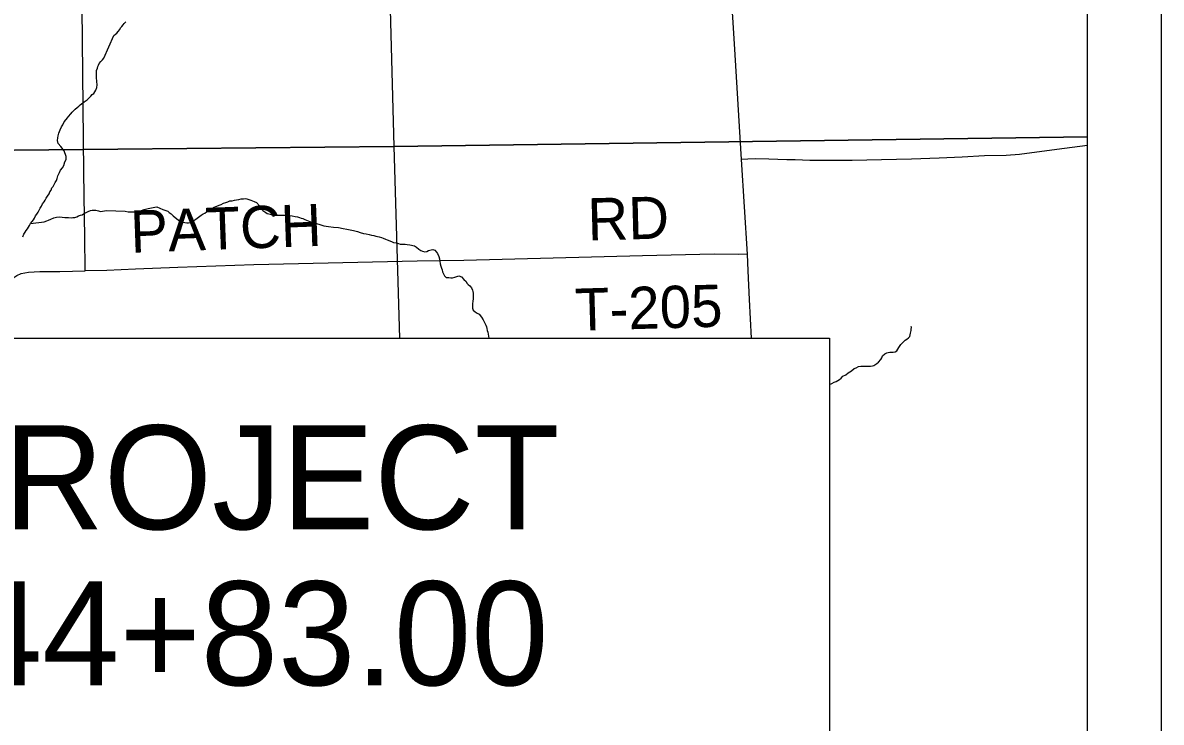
# Model space of a CAD drawing. Extents: x 10.6 to 44.6, y -2.6 to 23.4.
# Drawn here: x 18.57 to 20.103, y 19.074 to 20.016 of the extents above; entities that cross this region are included whole.
import ezdxf

# ---------------------------------------------------------------- set-up
doc = ezdxf.new("R2010")
doc.units = 0
for name, color, linetype in [('GM_X_County', 7, 'Continuous'), ('GM_X_County_Road', 7, 'Continuous'), ('GM_X_Minor_River', 7, 'Continuous'), ('GM_X_Section', 7, 'Continuous'), ('GM_X_Township', 7, 'Continuous'), ('GM_X_Township_Road', 7, 'Continuous'), ('GM_X_Township_Road_Text', 7, 'Continuous'), ('SH_Border', 7, 'Continuous'), ('SH_Data', 7, 'Continuous'), ('SH_Text', 7, 'Continuous')]:
    doc.layers.add(name, color=color, linetype=linetype)

msp = doc.modelspace()

# ---------------------------------------------------------------- linework, layer by layer
at = {"layer": 'GM_X_County'}
msp.add_lwpolyline([(20.0033, 15.5302), (20.0033, 22.3267), (13.2033, 22.3267), (13.2033, 15.5267), (19.8413, 15.5267)], dxfattribs=at)
at = {"layer": 'GM_X_County_Road'}
for points in [[(18.6535, 19.6817), (18.6533, 19.7284), (18.6525, 19.7533), (18.6516, 19.8149), (18.6497, 20.0361), (18.6472, 20.3469), (18.6468, 20.3934), (18.645, 20.5569), (18.6444, 20.6072), (18.643, 20.7692), (18.6417, 20.8913), (18.6416, 20.9277), (18.6445, 20.9403), (18.6498, 20.9497), (18.669, 20.9792), (18.7118, 21.0385)], [(19.5512, 19.5913), (19.5484, 19.6433), (19.5465, 19.6819), (19.5455, 19.7043), (19.5377, 19.8318), (19.5279, 19.9874), (19.5216, 20.0873), (19.5206, 20.1073), (19.5206, 20.1237), (19.5228, 20.1393), (19.526, 20.1578), (19.5311, 20.1832), (19.5709, 20.373), (19.5968, 20.5034), (19.6117, 20.5772), (19.6346, 20.6932), (19.6468, 20.7569), (19.6737, 20.9017), (19.6783, 20.9093)], [(18.5472, 19.661), (18.552, 19.6675), (18.5574, 19.6727), (18.5616, 19.6756), (18.5673, 19.6782), (18.5772, 19.68), (18.5926, 19.6811), (18.6194, 19.6811), (18.6535, 19.6817)]]:
    msp.add_lwpolyline(points, dxfattribs=at)
at = {"layer": 'GM_X_Minor_River'}
for points in [[(18.6789, 19.9682), (18.6923, 19.9989), (18.6942, 20.0004), (18.6961, 20.002), (18.698, 20.0043), (18.7002, 20.0069), (18.7013, 20.0089), (18.7028, 20.0108), (18.7047, 20.0131), (18.7062, 20.015), (18.7085, 20.0173)], [(18.6114, 19.7972), (18.6132, 19.8007), (18.6151, 19.8034), (18.6158, 19.8064), (18.6168, 19.8099), (18.619, 19.8141), (18.6205, 19.8172), (18.6231, 19.8207), (18.6249, 19.8237), (18.6263, 19.8287), (18.6281, 19.8318), (18.6281, 19.836), (18.6252, 19.8435), (18.6209, 19.8495), (18.6174, 19.8532), (18.6162, 19.8574), (18.6169, 19.8608), (18.6172, 19.8635), (18.6183, 19.8673), (18.6197, 19.8719), (18.6219, 19.8757), (18.6234, 19.8784), (18.6255, 19.8827), (18.6278, 19.8858), (18.6296, 19.8877), (18.6311, 19.8896), (18.6341, 19.8931), (18.6359, 19.8954), (18.6378, 19.8974), (18.64, 19.8997), (18.6426, 19.9017), (18.6449, 19.9036), (18.6467, 19.9055), (18.6486, 19.9067), (18.652, 19.9095), (18.6561, 19.9122), (18.6591, 19.9149), (18.661, 19.9169), (18.6632, 19.9192), (18.6651, 19.9208), (18.668, 19.925), (18.6691, 19.9285), (18.6698, 19.9323), (18.6693, 19.9368), (18.6688, 19.9421), (18.6687, 19.9448), (18.6687, 19.9482), (18.669, 19.9516), (18.67, 19.9547), (18.6708, 19.957), (18.6715, 19.9589), (18.6726, 19.9612), (18.6748, 19.9639), (18.6767, 19.9659), (18.6789, 19.9682)], [(18.5695, 19.7275), (18.5709, 19.7314), (18.5728, 19.7341), (18.5743, 19.736), (18.5757, 19.7383), (18.5772, 19.7406), (18.5787, 19.7429), (18.5801, 19.7456), (18.582, 19.7483), (18.5838, 19.7507), (18.5853, 19.753), (18.5868, 19.7557), (18.5883, 19.758), (18.5901, 19.7607), (18.5916, 19.7634), (18.593, 19.7661), (18.5949, 19.7691), (18.5963, 19.7722), (18.5982, 19.7749), (18.5996, 19.7772), (18.6011, 19.7799), (18.6029, 19.7826), (18.6052, 19.7857), (18.6059, 19.7884), (18.6077, 19.7907), (18.6088, 19.7934), (18.6103, 19.7953), (18.6114, 19.7972)], [(18.6825, 19.7633), (18.7074, 19.7623), (18.7116, 19.7612), (18.7142, 19.7612), (18.718, 19.7612), (18.7218, 19.7613), (18.7237, 19.7613), (18.7279, 19.7628), (18.7328, 19.7644), (18.7366, 19.7652), (18.7385, 19.7656), (18.7476, 19.7675), (18.7502, 19.7679), (18.754, 19.7664), (18.7582, 19.7646), (18.762, 19.7631), (18.7647, 19.762), (18.7666, 19.7604), (18.7693, 19.7586), (18.7719, 19.7559), (18.7746, 19.7537), (18.7765, 19.7522), (18.7792, 19.7499), (18.7811, 19.748), (18.7845, 19.7473), (18.788, 19.7469), (18.7906, 19.7466), (18.7929, 19.7466), (18.7955, 19.747), (18.7974, 19.7481), (18.7997, 19.7497), (18.8027, 19.7516), (18.8061, 19.7543), (18.8099, 19.7566), (18.8125, 19.7585), (18.8148, 19.7597), (18.8171, 19.7612), (18.8208, 19.7635), (18.8246, 19.7658), (18.8265, 19.767), (18.8341, 19.7701), (18.8367, 19.7712), (18.8398, 19.7728), (18.8428, 19.7739), (18.8458, 19.7747), (18.8485, 19.7759), (18.8515, 19.7763), (18.8549, 19.7771), (18.8576, 19.7775), (18.8606, 19.7779), (18.8636, 19.7786), (18.8667, 19.7787), (18.8689, 19.7791), (18.8712, 19.7787), (18.8739, 19.7779), (18.8765, 19.7772), (18.8788, 19.7761), (18.8811, 19.7753), (18.8841, 19.7738), (18.8861, 19.772), (18.8872, 19.7701), (18.8887, 19.7682), (18.8899, 19.7663), (18.893, 19.7633), (18.8968, 19.7603), (18.8987, 19.7591), (18.901, 19.7584), (18.9029, 19.758), (18.9051, 19.7573), (18.907, 19.7569), (18.9089, 19.7569), (18.9116, 19.7569), (18.915, 19.7566), (18.9203, 19.7566), (18.9245, 19.7567), (18.9287, 19.7563), (18.9325, 19.756), (18.9363, 19.7552), (18.9397, 19.7545), (18.9424, 19.7538), (18.9443, 19.753), (18.9466, 19.7523), (18.9492, 19.7511), (18.9606, 19.7467), (18.9652, 19.7456), (18.9698, 19.7441), (18.9751, 19.7426), (18.9812, 19.7415), (18.988, 19.7408), (18.9948, 19.7401), (19.0009, 19.739), (19.0059, 19.7379), (19.0104, 19.7371), (19.015, 19.736), (19.0203, 19.7346), (19.0241, 19.7335), (19.0283, 19.7323)], [(18.5801, 19.7456), (18.5984, 19.7479), (18.6018, 19.7491), (18.604, 19.7499), (18.6074, 19.7515), (18.6112, 19.7531), (18.615, 19.754), (18.6188, 19.7544), (18.6226, 19.7542), (18.626, 19.7538), (18.6287, 19.7535), (18.6313, 19.7536), (18.6348, 19.7533), (18.637, 19.7537), (18.6397, 19.7538), (18.6423, 19.7546), (18.6446, 19.7558), (18.6472, 19.7566), (18.6495, 19.7574), (18.6514, 19.7586), (18.6533, 19.7594), (18.6578, 19.7618), (18.6608, 19.763), (18.6631, 19.7634), (18.665, 19.7634), (18.668, 19.7635), (18.6715, 19.7628), (18.6741, 19.7617), (18.6825, 19.7633)], [(19.0283, 19.7323), (19.0321, 19.7316), (19.0359, 19.7309), (19.0393, 19.7298), (19.0424, 19.7294), (19.045, 19.7287), (19.0473, 19.7279), (19.0496, 19.7276), (19.0526, 19.7268), (19.0549, 19.7257), (19.058, 19.7246), (19.0602, 19.7238), (19.0637, 19.7223), (19.0671, 19.7208), (19.069, 19.7201), (19.0724, 19.7194), (19.0755, 19.7186), (19.0778, 19.7179), (19.0796, 19.7179), (19.0819, 19.7179), (19.0846, 19.7176), (19.0872, 19.7172), (19.0907, 19.7168), (19.0929, 19.7165), (19.0948, 19.7161), (19.0971, 19.7154), (19.0998, 19.7139), (19.1029, 19.7112), (19.1055, 19.7093), (19.1078, 19.7082), (19.1108, 19.7075), (19.1135, 19.7079), (19.1161, 19.7094), (19.1196, 19.7102), (19.1218, 19.7106), (19.1245, 19.7095), (19.1268, 19.7068), (19.1279, 19.705), (19.1299, 19.7012), (19.1307, 19.6978), (19.1311, 19.6951), (19.1318, 19.6913), (19.1326, 19.6883), (19.1334, 19.6856), (19.1342, 19.683), (19.135, 19.6807), (19.1361, 19.678), (19.1377, 19.675), (19.1396, 19.6731), (19.1434, 19.6728), (19.146, 19.6724), (19.1483, 19.6724), (19.1513, 19.6732), (19.1566, 19.6751), (19.1604, 19.6737), (19.1635, 19.6703), (19.1666, 19.6676), (19.1677, 19.6653), (19.1692, 19.6635), (19.1715, 19.6616), (19.1738, 19.6589), (19.1754, 19.6559), (19.1758, 19.654), (19.1762, 19.6517), (19.1762, 19.6487), (19.1762, 19.6445), (19.1755, 19.6407), (19.1751, 19.638), (19.1751, 19.6361), (19.1752, 19.6339), (19.1752, 19.6316), (19.176, 19.6289), (19.1786, 19.6267), (19.1817, 19.6248), (19.1844, 19.6233), (19.1874, 19.6195), (19.1897, 19.6161), (19.1916, 19.6123), (19.1932, 19.6089), (19.194, 19.6066), (19.1947, 19.6044), (19.1951, 19.6017), (19.1959, 19.5991), (19.1967, 19.5941), (19.1974, 19.5913)], [(19.6562, 19.5288), (19.6591, 19.5302), (19.6625, 19.5318), (19.6651, 19.5329), (19.6674, 19.5341), (19.6697, 19.5356), (19.6719, 19.5372), (19.6742, 19.5399), (19.678, 19.5418), (19.681, 19.5445), (19.6836, 19.546), (19.6855, 19.5472), (19.6893, 19.5502), (19.6919, 19.5514), (19.6953, 19.5529), (19.6984, 19.5537), (19.7022, 19.5537), (19.706, 19.5534), (19.7094, 19.5534), (19.7113, 19.5534), (19.7139, 19.5538), (19.7158, 19.5542), (19.7196, 19.5573), (19.7219, 19.5588), (19.7253, 19.5626), (19.7264, 19.5649), (19.7275, 19.5672), (19.7305, 19.5703), (19.7332, 19.5714), (19.7351, 19.5718), (19.7373, 19.5722), (19.74, 19.5723), (19.7419, 19.5723), (19.7445, 19.573), (19.7468, 19.5742), (19.7494, 19.5788), (19.752, 19.5826), (19.7551, 19.586), (19.7581, 19.5883), (19.7603, 19.5899), (19.7622, 19.5918), (19.7641, 19.5933), (19.7652, 19.5979), (19.7659, 19.6013), (19.7659, 19.6032), (19.7663, 19.6055), (19.7659, 19.607)]]:
    msp.add_lwpolyline(points, dxfattribs=at)
at = {"layer": 'GM_X_Section'}
for p, q in [((20.0033, 19.8622), (20.0033, 20.629)), ((20.0033, 18.797), (20.0033, 19.8622))]:
    msp.add_line(p, q, dxfattribs=at)
for points in [[(20.0033, 20.629), (19.9973, 20.9555), (19.4928, 20.9481), (19.0401, 20.9394), (19.0693, 19.8492), (20.0033, 19.8622)], [(20.0033, 19.8622), (19.0693, 19.8492), (19.0768, 19.5913)], [(18.1454, 19.5913), (18.1394, 19.8405), (19.0693, 19.8492), (19.0768, 19.5913)]]:
    msp.add_lwpolyline(points, dxfattribs=at)
msp.add_lwpolyline([(19.0401, 20.9394), (19.0693, 19.8492), (18.1394, 19.8405), (18.1171, 20.9247), (18.1295, 20.9248), (18.5902, 20.929), (19.0353, 20.9393)], close=True, dxfattribs=at)
at = {"layer": 'GM_X_Township'}
msp.add_line((20.0033, 15.5302), (20.0033, 20.9573), dxfattribs=at)
at = {"layer": 'GM_X_Township_Road'}
for points in [[(20.0033, 19.8507), (19.9622, 19.8451), (19.9121, 19.8387), (19.8939, 19.837), (19.865, 19.8367), (19.8345, 19.8351), (19.8038, 19.8334), (19.7663, 19.832), (19.7262, 19.8311), (19.6865, 19.8303), (19.6583, 19.8303), (19.6405, 19.8306), (19.6295, 19.8306), (19.6197, 19.8308), (19.61, 19.8313), (19.5987, 19.8313), (19.5863, 19.8318), (19.5743, 19.8321), (19.5565, 19.8325), (19.5462, 19.8323), (19.5377, 19.8318)], [(19.5455, 19.7043), (19.5338, 19.704), (19.5006, 19.7041), (19.4041, 19.7021), (19.1634, 19.6957), (19.1007, 19.6951), (18.8805, 19.6901), (18.7783, 19.6864), (18.7215, 19.6839), (18.6826, 19.6823), (18.6535, 19.6817)]]:
    msp.add_lwpolyline(points, dxfattribs=at)
at = {"layer": 'SH_Border'}
msp.add_lwpolyline([(17.8388, 19.5913), (19.6562, 19.5913), (19.6562, 19.0263), (17.8388, 19.0263)], close=True, dxfattribs=at)
at = {"layer": 'SH_Data'}
msp.add_line((20.1028, 22.4265), (20.1028, 15.4265), dxfattribs=at)

# ---------------------------------------------------------------- texts
at = {"layer": 'GM_X_Township_Road_Text'}
for s, rotation, p in [('RD', 1.4826, (19.3308, 19.7227)), ('PATCH', 2.0965, (18.7154, 19.7061)), ('T-205', 1.6848, (19.3142, 19.601))]:
    msp.add_text(s, height=0.05682, rotation=rotation, dxfattribs=at).set_placement(p)
at = {"layer": 'SH_Text'}
for s, p in [('END PROJECT', (17.9714, 19.3338)), ('STA 644+83.00', (17.9714, 19.1238))]:
    msp.add_text(s, height=0.14, dxfattribs=at).set_placement(p)

doc.saveas('drawing.dxf')
